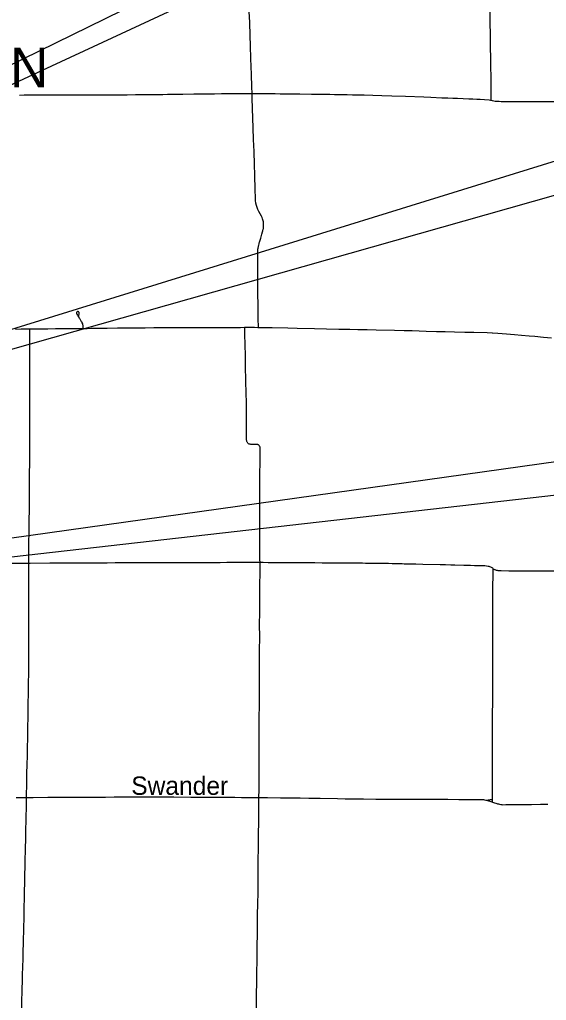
# Model space of a CAD drawing. Extents: x 1772825 to 1773716, y 1138558 to 1139032.
# Drawn here: x 1773418.9 to 1773464.2, y 1138829.3 to 1138913.7 of the extents above; entities that cross this region are included whole.
import ezdxf

# ---------------------------------------------------------------- set-up
doc = ezdxf.new("R2010")
doc.units = 0
for name, color, linetype in [('GM_X_County_Road', 7, 'Continuous'), ('GM_X_State_Route', 7, 'Continuous'), ('GM_X_Township_Road', 7, 'Continuous'), ('GM_X_Township_Text', 7, 'Continuous'), ('GM_X_Unincorporated_Text', 7, 'Continuous'), ('SH_Text', 7, 'Continuous')]:
    doc.layers.add(name, color=color, linetype=linetype)

msp = doc.modelspace()

# ---------------------------------------------------------------- linework, layer by layer
at = {"layer": 'GM_X_County_Road'}
for points in [[(1773459.466, 1138906.727), (1773459.463, 1138907.253), (1773459.452, 1138908.782), (1773459.442, 1138909.524), (1773459.431, 1138910.407), (1773459.42, 1138911.215), (1773459.408, 1138912.222), (1773459.38, 1138913.514), (1773459.377, 1138914.41), (1773459.362, 1138915.504), (1773459.358, 1138915.951), (1773459.347, 1138916.685), (1773459.32, 1138918.12), (1773459.275, 1138920.638), (1773459.261, 1138921.334), (1773459.249, 1138921.744), (1773459.231, 1138922.589), (1773459.214, 1138923.403), (1773459.198, 1138924.181), (1773459.16, 1138926.244), (1773459.162, 1138926.691)], [(1773439.599, 1138866.982), (1773439.593, 1138867.207), (1773439.587, 1138867.394), (1773439.587, 1138867.722), (1773439.58, 1138868.537), (1773439.587, 1138869.854), (1773439.586, 1138871.209), (1773439.589, 1138872.514), (1773439.59, 1138873.782), (1773439.591, 1138874.714), (1773439.6, 1138875.448), (1773439.611, 1138876.442), (1773439.619, 1138876.753), (1773439.614, 1138876.798), (1773439.607, 1138876.851), (1773439.601, 1138876.879), (1773439.591, 1138876.915), (1773439.58, 1138876.942), (1773439.558, 1138876.982), (1773439.53, 1138877.017), (1773439.506, 1138877.044), (1773439.47, 1138877.072), (1773439.44, 1138877.091), (1773439.408, 1138877.105), (1773439.374, 1138877.113), (1773439.325, 1138877.119), (1773439.243, 1138877.122), (1773438.906, 1138877.117), (1773438.805, 1138877.122), (1773438.752, 1138877.129), (1773438.716, 1138877.136), (1773438.662, 1138877.153), (1773438.619, 1138877.174), (1773438.581, 1138877.2), (1773438.546, 1138877.228), (1773438.507, 1138877.277), (1773438.481, 1138877.326), (1773438.466, 1138877.364), (1773438.451, 1138877.415), (1773438.441, 1138877.477), (1773438.442, 1138877.539), (1773438.444, 1138878.224), (1773438.441, 1138878.944), (1773438.438, 1138879.749), (1773438.423, 1138880.667), (1773438.386, 1138882.493), (1773438.351, 1138883.934), (1773438.336, 1138884.778), (1773438.291, 1138886.606), (1773438.279, 1138887.099), (1773438.277, 1138887.19)], [(1773419.727, 1138866.916), (1773419.843, 1138866.918), (1773421.52, 1138866.926), (1773422.455, 1138866.929), (1773422.664, 1138866.931), (1773422.813, 1138866.932), (1773423.061, 1138866.933), (1773423.668, 1138866.934), (1773423.88, 1138866.934), (1773424.091, 1138866.935), (1773424.364, 1138866.937), (1773424.749, 1138866.937), (1773425.706, 1138866.945), (1773426.452, 1138866.946), (1773427.149, 1138866.954), (1773427.77, 1138866.956), (1773428.28, 1138866.959), (1773428.839, 1138866.962), (1773429.635, 1138866.966), (1773430.394, 1138866.972), (1773431.077, 1138866.971), (1773432.445, 1138866.978), (1773433.713, 1138866.978), (1773434.645, 1138866.976), (1773435.242, 1138866.978), (1773435.677, 1138866.977), (1773436.174, 1138866.979), (1773436.746, 1138866.98), (1773437.206, 1138866.982), (1773437.914, 1138866.983), (1773438.424, 1138866.983), (1773438.61, 1138866.982), (1773438.709, 1138866.983), (1773438.784, 1138866.982), (1773439.206, 1138866.981), (1773439.468, 1138866.982), (1773439.599, 1138866.982)], [(1773439.505, 1138846.749), (1773439.51, 1138847.409), (1773439.518, 1138848.363), (1773439.517, 1138849.159), (1773439.523, 1138850.427), (1773439.525, 1138850.936), (1773439.533, 1138852.201), (1773439.535, 1138853.207), (1773439.539, 1138855.084), (1773439.539, 1138855.706), (1773439.544, 1138856.638), (1773439.545, 1138857.098), (1773439.553, 1138857.969), (1773439.561, 1138859.456), (1773439.567, 1138860.475), (1773439.566, 1138861.705), (1773439.568, 1138862.575), (1773439.581, 1138864.066), (1773439.587, 1138864.899), (1773439.604, 1138866.217), (1773439.604, 1138866.603), (1773439.6, 1138866.93), (1773439.599, 1138866.982)], [(1773439.599, 1138866.982), (1773439.642, 1138866.982), (1773439.853, 1138866.982), (1773440.3, 1138866.978), (1773440.723, 1138866.978), (1773441.531, 1138866.975), (1773442.414, 1138866.966), (1773443.259, 1138866.962), (1773444.316, 1138866.954), (1773444.938, 1138866.95), (1773445.373, 1138866.95), (1773446.653, 1138866.944), (1773447.188, 1138866.942), (1773447.498, 1138866.939), (1773447.819, 1138866.932), (1773447.894, 1138866.932), (1773448.403, 1138866.922), (1773448.664, 1138866.917), (1773449.174, 1138866.913), (1773449.323, 1138866.91), (1773449.435, 1138866.91), (1773449.834, 1138866.91), (1773450.23, 1138866.904), (1773450.651, 1138866.899), (1773450.962, 1138866.891), (1773451.124, 1138866.887), (1773451.819, 1138866.869), (1773451.981, 1138866.862), (1773452.254, 1138866.855), (1773452.403, 1138866.852), (1773452.689, 1138866.843), (1773452.863, 1138866.838), (1773452.975, 1138866.837), (1773453.584, 1138866.829), (1773455.075, 1138866.795), (1773455.547, 1138866.78), (1773455.983, 1138866.77), (1773456.355, 1138866.759), (1773457.113, 1138866.742), (1773457.325, 1138866.735), (1773457.536, 1138866.731), (1773457.685, 1138866.726), (1773458.033, 1138866.719), (1773458.755, 1138866.704), (1773458.852, 1138866.7), (1773458.927, 1138866.696), (1773459.062, 1138866.682), (1773459.195, 1138866.66), (1773459.266, 1138866.643), (1773459.312, 1138866.629), (1773459.413, 1138866.59), (1773459.478, 1138866.561), (1773459.518, 1138866.536), (1773459.566, 1138866.503), (1773459.606, 1138866.469), (1773459.644, 1138866.431)], [(1773418.264, 1138866.898), (1773419.433, 1138866.912), (1773419.727, 1138866.916)], [(1773418.645, 1138846.756), (1773419.328, 1138846.758), (1773419.532, 1138846.759)], [(1773419.532, 1138846.759), (1773420.099, 1138846.761), (1773421.355, 1138846.775), (1773421.777, 1138846.777), (1773422.138, 1138846.779), (1773422.871, 1138846.781), (1773423.729, 1138846.791), (1773424.463, 1138846.789), (1773426.302, 1138846.791), (1773427.048, 1138846.799), (1773428.453, 1138846.801), (1773429.212, 1138846.8), (1773430.219, 1138846.799), (1773430.977, 1138846.803), (1773431.474, 1138846.805), (1773432.195, 1138846.801), (1773433.65, 1138846.788), (1773434.247, 1138846.783), (1773435.092, 1138846.777), (1773435.602, 1138846.774), (1773436.372, 1138846.774), (1773436.783, 1138846.776), (1773437.429, 1138846.774), (1773438.001, 1138846.768), (1773438.324, 1138846.761), (1773438.622, 1138846.755), (1773438.734, 1138846.754), (1773439.119, 1138846.75), (1773439.48, 1138846.749), (1773439.505, 1138846.749)], [(1773439.271, 1138826.489), (1773439.27, 1138826.524), (1773439.268, 1138827.016), (1773439.274, 1138827.537), (1773439.288, 1138828.903), (1773439.298, 1138829.661), (1773439.318, 1138831.015), (1773439.325, 1138831.624), (1773439.338, 1138832.817), (1773439.35, 1138833.973), (1773439.367, 1138835.029), (1773439.38, 1138835.911), (1773439.393, 1138836.706), (1773439.409, 1138837.588), (1773439.424, 1138838.607), (1773439.437, 1138840.397), (1773439.44, 1138841.006), (1773439.47, 1138842.772), (1773439.479, 1138843.555), (1773439.489, 1138844.71), (1773439.496, 1138846.153), (1773439.504, 1138846.687), (1773439.505, 1138846.749)], [(1773439.505, 1138846.749), (1773440.238, 1138846.743), (1773441.357, 1138846.731), (1773442.028, 1138846.724), (1773443.048, 1138846.713), (1773443.794, 1138846.701), (1773444.763, 1138846.687), (1773446.242, 1138846.663), (1773446.901, 1138846.653), (1773447.697, 1138846.64), (1773448.505, 1138846.636), (1773449.561, 1138846.622), (1773450.879, 1138846.615), (1773452.085, 1138846.609), (1773452.719, 1138846.61), (1773452.868, 1138846.609), (1773453.067, 1138846.606), (1773453.366, 1138846.603), (1773453.726, 1138846.601), (1773454.136, 1138846.601), (1773454.521, 1138846.601), (1773455.106, 1138846.6), (1773455.74, 1138846.598), (1773456.685, 1138846.596), (1773457.132, 1138846.593), (1773457.442, 1138846.59), (1773457.94, 1138846.59), (1773458.225, 1138846.591), (1773458.537, 1138846.588), (1773458.699, 1138846.581), (1773458.76, 1138846.577), (1773458.819, 1138846.568), (1773458.898, 1138846.555), (1773458.993, 1138846.532)], [(1773458.993, 1138846.532), (1773459.032, 1138846.523), (1773459.248, 1138846.461), (1773459.432, 1138846.402), (1773459.57, 1138846.362)]]:
    msp.add_lwpolyline(points, dxfattribs=at)
at = {"layer": 'GM_X_State_Route'}
for points in [[(1773420.858, 1138887.062), (1773420.876, 1138887.062), (1773421.348, 1138887.067), (1773422.007, 1138887.081), (1773422.628, 1138887.085), (1773423.187, 1138887.088), (1773423.92, 1138887.094), (1773423.97, 1138887.095), (1773424.181, 1138887.095), (1773424.395, 1138887.098), (1773424.74, 1138887.101), (1773425.089, 1138887.107), (1773425.561, 1138887.113), (1773425.772, 1138887.116), (1773426.468, 1138887.128), (1773427.338, 1138887.137), (1773428.109, 1138887.146), (1773428.805, 1138887.147), (1773429.738, 1138887.156), (1773430.471, 1138887.164), (1773430.981, 1138887.174), (1773432.013, 1138887.173), (1773432.783, 1138887.177), (1773433.815, 1138887.176), (1773434.474, 1138887.18), (1773435.17, 1138887.181), (1773436.165, 1138887.188), (1773436.836, 1138887.184), (1773437.383, 1138887.187), (1773437.905, 1138887.189), (1773438.277, 1138887.19), (1773438.676, 1138887.192), (1773439.123, 1138887.19), (1773439.409, 1138887.186), (1773439.455, 1138887.185), (1773439.944, 1138887.178), (1773440.652, 1138887.168), (1773441.995, 1138887.14), (1773442.79, 1138887.121), (1773444.282, 1138887.092), (1773445.301, 1138887.068), (1773446.357, 1138887.044), (1773446.904, 1138887.035), (1773447.314, 1138887.028), (1773448.01, 1138887.014), (1773448.806, 1138886.998), (1773449.576, 1138886.976), (1773451.142, 1138886.944), (1773451.974, 1138886.922), (1773452.646, 1138886.905), (1773452.671, 1138886.904), (1773453.864, 1138886.872), (1773454.771, 1138886.845), (1773455.516, 1138886.827), (1773456.324, 1138886.806), (1773457.207, 1138886.783), (1773457.965, 1138886.762), (1773459.133, 1138886.732), (1773459.544, 1138886.715), (1773459.581, 1138886.714), (1773460.04, 1138886.686), (1773460.796, 1138886.629), (1773461.478, 1138886.574), (1773462.085, 1138886.519), (1773462.716, 1138886.461), (1773463.211, 1138886.417), (1773463.954, 1138886.354), (1773464.657, 1138886.299)], [(1773418.576, 1138887.045), (1773419.074, 1138887.048), (1773419.161, 1138887.048), (1773419.372, 1138887.048), (1773419.819, 1138887.052), (1773420.858, 1138887.062)]]:
    msp.add_lwpolyline(points, dxfattribs=at)
at = {"layer": 'GM_X_Township_Road'}
for points in [[(1773438.912, 1138907.304), (1773438.902, 1138907.864), (1773438.868, 1138908.945), (1773438.819, 1138910.312), (1773438.783, 1138911.393), (1773438.75, 1138912.287), (1773438.707, 1138913.418), (1773438.678, 1138914.35)], [(1773418.917, 1138907.161), (1773419.327, 1138907.172), (1773419.712, 1138907.177), (1773419.886, 1138907.178), (1773420.023, 1138907.179), (1773420.197, 1138907.181), (1773420.482, 1138907.184), (1773420.756, 1138907.187), (1773420.967, 1138907.187), (1773421.141, 1138907.187), (1773421.887, 1138907.187), (1773422.086, 1138907.186), (1773422.297, 1138907.185), (1773422.745, 1138907.184), (1773423.279, 1138907.184), (1773423.665, 1138907.185), (1773423.901, 1138907.186), (1773424.1, 1138907.187), (1773424.261, 1138907.187), (1773424.473, 1138907.188), (1773424.783, 1138907.189), (1773425.218, 1138907.189), (1773425.492, 1138907.19), (1773425.653, 1138907.191), (1773425.865, 1138907.191), (1773426.66, 1138907.188), (1773427.493, 1138907.192), (1773428.165, 1138907.196), (1773428.898, 1138907.203), (1773429.781, 1138907.214), (1773430.738, 1138907.221), (1773431.236, 1138907.223), (1773431.658, 1138907.229), (1773432.417, 1138907.24), (1773432.976, 1138907.246), (1773433.909, 1138907.258), (1773434.468, 1138907.269), (1773434.716, 1138907.275), (1773434.828, 1138907.276), (1773435.238, 1138907.279), (1773435.673, 1138907.281), (1773436.283, 1138907.286), (1773436.63, 1138907.29), (1773437.178, 1138907.288), (1773437.439, 1138907.289), (1773437.836, 1138907.292), (1773438.01, 1138907.293), (1773438.309, 1138907.296), (1773438.912, 1138907.304)], [(1773438.912, 1138907.304), (1773438.955, 1138907.305), (1773439.514, 1138907.307), (1773439.974, 1138907.305), (1773440.223, 1138907.303), (1773440.583, 1138907.298), (1773440.894, 1138907.292), (1773441.316, 1138907.282), (1773441.814, 1138907.273), (1773442.05, 1138907.271), (1773442.61, 1138907.268), (1773443.02, 1138907.264), (1773444.014, 1138907.254), (1773444.3, 1138907.252), (1773445.083, 1138907.241), (1773445.605, 1138907.233), (1773445.991, 1138907.227), (1773446.774, 1138907.214), (1773447.085, 1138907.208), (1773447.557, 1138907.198), (1773448.539, 1138907.18), (1773449.297, 1138907.159), (1773450.08, 1138907.135), (1773450.924, 1138907.104), (1773452.092, 1138907.057), (1773453.683, 1138907), (1773454.279, 1138906.975), (1773455.211, 1138906.94), (1773455.745, 1138906.92), (1773456.155, 1138906.905), (1773456.577, 1138906.886), (1773457.558, 1138906.843), (1773457.881, 1138906.833), (1773458.242, 1138906.822), (1773458.527, 1138906.809), (1773458.899, 1138906.788), (1773459.295, 1138906.753), (1773459.405, 1138906.737), (1773459.466, 1138906.727)], [(1773439.395, 1138892.853), (1773439.395, 1138893.131), (1773439.398, 1138893.386), (1773439.401, 1138893.606), (1773439.403, 1138893.722), (1773439.41, 1138893.842), (1773439.42, 1138893.924), (1773439.429, 1138893.991), (1773439.439, 1138894.053), (1773439.454, 1138894.125), (1773439.47, 1138894.198), (1773439.487, 1138894.27), (1773439.512, 1138894.364), (1773439.537, 1138894.45), (1773439.556, 1138894.522), (1773439.656, 1138894.872), (1773439.747, 1138895.192), (1773439.813, 1138895.405), (1773439.842, 1138895.503), (1773439.869, 1138895.62), (1773439.884, 1138895.694), (1773439.898, 1138895.777), (1773439.905, 1138895.832), (1773439.91, 1138895.898), (1773439.91, 1138895.972), (1773439.909, 1138896.046), (1773439.905, 1138896.119), (1773439.895, 1138896.192), (1773439.884, 1138896.26), (1773439.864, 1138896.349), (1773439.817, 1138896.515), (1773439.771, 1138896.642), (1773439.719, 1138896.753), (1773439.604, 1138896.958), (1773439.5, 1138897.143), (1773439.42, 1138897.313), (1773439.349, 1138897.5), (1773439.295, 1138897.68), (1773439.251, 1138897.876), (1773439.222, 1138898.086), (1773439.209, 1138898.298), (1773439.187, 1138899.055), (1773439.152, 1138900.285), (1773439.122, 1138901.204), (1773439.087, 1138902.298), (1773439.048, 1138903.354), (1773439.015, 1138904.335), (1773438.961, 1138906), (1773438.919, 1138906.907), (1773438.912, 1138907.304)], [(1773459.466, 1138906.727), (1773459.564, 1138906.7), (1773459.682, 1138906.673), (1773459.82, 1138906.65), (1773459.925, 1138906.64), (1773460.004, 1138906.633), (1773460.152, 1138906.627), (1773460.33, 1138906.625), (1773461.56, 1138906.619), (1773462.592, 1138906.615), (1773463.549, 1138906.609), (1773464.643, 1138906.606), (1773465.168, 1138906.601)], [(1773439.406, 1138891.652), (1773439.403, 1138891.853), (1773439.399, 1138892.461), (1773439.395, 1138892.853)], [(1773439.455, 1138887.185), (1773439.454, 1138887.281), (1773439.446, 1138887.856), (1773439.437, 1138888.84), (1773439.423, 1138890.37), (1773439.406, 1138891.652)], [(1773424.395, 1138887.098), (1773424.389, 1138887.274), (1773424.388, 1138887.309), (1773424.383, 1138887.346), (1773424.375, 1138887.399), (1773424.354, 1138887.478), (1773424.322, 1138887.566), (1773424.297, 1138887.62), (1773424.266, 1138887.675), (1773424.237, 1138887.719), (1773424.168, 1138887.828), (1773424.127, 1138887.889), (1773424.083, 1138887.963), (1773424.041, 1138888.029), (1773424.032, 1138888.07), (1773424.03, 1138888.106), (1773424.035, 1138888.183), (1773424.053, 1138888.391), (1773424.054, 1138888.415), (1773424.053, 1138888.441), (1773424.05, 1138888.459), (1773424.045, 1138888.477), (1773424.033, 1138888.499), (1773424.017, 1138888.517), (1773423.997, 1138888.531), (1773423.962, 1138888.543), (1773423.937, 1138888.544), (1773423.913, 1138888.541), (1773423.879, 1138888.526), (1773423.864, 1138888.515), (1773423.851, 1138888.502), (1773423.833, 1138888.476), (1773423.827, 1138888.453), (1773423.825, 1138888.435), (1773423.826, 1138888.41), (1773423.833, 1138888.374), (1773423.851, 1138888.327), (1773423.902, 1138888.235), (1773423.942, 1138888.17), (1773423.98, 1138888.116), (1773424.016, 1138888.083)], [(1773419.812, 1138876.794), (1773419.811, 1138876.849), (1773419.811, 1138876.997), (1773419.812, 1138877.395), (1773419.812, 1138877.494), (1773419.813, 1138877.892), (1773419.812, 1138878.066), (1773419.813, 1138878.153), (1773419.814, 1138878.662), (1773419.817, 1138879.272), (1773419.816, 1138879.471), (1773419.814, 1138879.67), (1773419.817, 1138880.204), (1773419.817, 1138880.801), (1773419.815, 1138881.149), (1773419.813, 1138881.708), (1773419.814, 1138882.068), (1773419.816, 1138882.392), (1773419.818, 1138882.889), (1773419.818, 1138884.207), (1773419.818, 1138884.542), (1773419.82, 1138885.425), (1773419.822, 1138885.735), (1773419.822, 1138886.357), (1773419.822, 1138886.742), (1773419.82, 1138886.879), (1773419.819, 1138887.052)], [(1773419.727, 1138866.916), (1773419.727, 1138866.992), (1773419.727, 1138867.029), (1773419.727, 1138867.065), (1773419.727, 1138867.114), (1773419.726, 1138867.213), (1773419.727, 1138867.324), (1773419.728, 1138867.411), (1773419.73, 1138867.573), (1773419.731, 1138867.684), (1773419.733, 1138867.958), (1773419.735, 1138868.095), (1773419.737, 1138868.405), (1773419.738, 1138868.53), (1773419.737, 1138868.753), (1773419.737, 1138868.977), (1773419.741, 1138869.262), (1773419.756, 1138870.188), (1773419.757, 1138870.493), (1773419.766, 1138870.89), (1773419.771, 1138871.213), (1773419.776, 1138871.55), (1773419.781, 1138871.843), (1773419.78, 1138872.07), (1773419.782, 1138872.231), (1773419.785, 1138872.455), (1773419.787, 1138872.604), (1773419.785, 1138873.064), (1773419.785, 1138873.363), (1773419.784, 1138873.462), (1773419.784, 1138873.598), (1773419.785, 1138873.834), (1773419.784, 1138874.094), (1773419.786, 1138874.156), (1773419.795, 1138874.964), (1773419.798, 1138875.151), (1773419.802, 1138875.479), (1773419.806, 1138875.76), (1773419.808, 1138875.934), (1773419.809, 1138876.033), (1773419.811, 1138876.232), (1773419.81, 1138876.306), (1773419.811, 1138876.404), (1773419.813, 1138876.688), (1773419.813, 1138876.738), (1773419.812, 1138876.794)], [(1773419.532, 1138846.759), (1773419.537, 1138847.062), (1773419.546, 1138847.746), (1773419.55, 1138848.18), (1773419.564, 1138848.802), (1773419.583, 1138849.634), (1773419.598, 1138850.305), (1773419.605, 1138850.741), (1773419.634, 1138852.182), (1773419.641, 1138852.63), (1773419.649, 1138853.102), (1773419.655, 1138853.388), (1773419.663, 1138853.897), (1773419.673, 1138854.729), (1773419.683, 1138855.151), (1773419.689, 1138855.386), (1773419.692, 1138855.485), (1773419.693, 1138855.585), (1773419.695, 1138855.795), (1773419.697, 1138855.894), (1773419.698, 1138855.956), (1773419.7, 1138856.092), (1773419.7, 1138856.191), (1773419.703, 1138856.291), (1773419.704, 1138856.389), (1773419.707, 1138856.588), (1773419.707, 1138856.674), (1773419.709, 1138856.773), (1773419.709, 1138856.848), (1773419.711, 1138856.972), (1773419.713, 1138857.071), (1773419.713, 1138857.157), (1773419.714, 1138857.244), (1773419.716, 1138857.442), (1773419.716, 1138857.517), (1773419.717, 1138857.628), (1773419.72, 1138857.777), (1773419.723, 1138858.175), (1773419.724, 1138858.386), (1773419.724, 1138858.821), (1773419.725, 1138859.219), (1773419.726, 1138859.605), (1773419.724, 1138860.002), (1773419.728, 1138860.561), (1773419.732, 1138861.208), (1773419.733, 1138861.581), (1773419.731, 1138862.078), (1773419.73, 1138862.252), (1773419.729, 1138862.438), (1773419.729, 1138862.524), (1773419.732, 1138862.647), (1773419.731, 1138862.883), (1773419.735, 1138863.494), (1773419.734, 1138863.745), (1773419.734, 1138864.474), (1773419.733, 1138864.697), (1773419.731, 1138864.97), (1773419.731, 1138865.094), (1773419.73, 1138865.231), (1773419.73, 1138865.579), (1773419.731, 1138865.753), (1773419.731, 1138866.15), (1773419.731, 1138866.249), (1773419.731, 1138866.348), (1773419.73, 1138866.472), (1773419.727, 1138866.732), (1773419.726, 1138866.818), (1773419.727, 1138866.916)], [(1773459.579, 1138846.596), (1773459.589, 1138846.796), (1773459.592, 1138847.281), (1773459.587, 1138848.648), (1773459.58, 1138849.356), (1773459.575, 1138850.313), (1773459.572, 1138851.482), (1773459.587, 1138853.632), (1773459.595, 1138855.273), (1773459.6, 1138856.416), (1773459.608, 1138857.932), (1773459.61, 1138858.79), (1773459.619, 1138860.891), (1773459.615, 1138862.593), (1773459.616, 1138863.464), (1773459.619, 1138864.806), (1773459.626, 1138865.937), (1773459.629, 1138866.08), (1773459.644, 1138866.431)], [(1773459.644, 1138866.431), (1773459.691, 1138866.4), (1773459.752, 1138866.366), (1773459.785, 1138866.351), (1773459.827, 1138866.335), (1773459.897, 1138866.313), (1773459.974, 1138866.295), (1773460.031, 1138866.287), (1773460.11, 1138866.278), (1773460.229, 1138866.269), (1773460.337, 1138866.269), (1773460.995, 1138866.262), (1773461.853, 1138866.262), (1773462.873, 1138866.259), (1773463.892, 1138866.248), (1773464.986, 1138866.24)], [(1773419.246, 1138833.528), (1773419.265, 1138834.188), (1773419.299, 1138835.629), (1773419.315, 1138836.325), (1773419.324, 1138836.71), (1773419.339, 1138837.481), (1773419.343, 1138837.903), (1773419.35, 1138838.326), (1773419.357, 1138838.798), (1773419.368, 1138839.32), (1773419.377, 1138839.73), (1773419.386, 1138840.103), (1773419.402, 1138840.811), (1773419.416, 1138841.445), (1773419.433, 1138842.128), (1773419.443, 1138842.563), (1773419.454, 1138843.01), (1773419.476, 1138843.967), (1773419.497, 1138844.763), (1773419.503, 1138845.222), (1773419.516, 1138845.744), (1773419.525, 1138846.291), (1773419.532, 1138846.759)], [(1773458.993, 1138846.532), (1773459.192, 1138846.548), (1773459.28, 1138846.554), (1773459.339, 1138846.56), (1773459.411, 1138846.571), (1773459.523, 1138846.587), (1773459.579, 1138846.596)], [(1773459.57, 1138846.362), (1773459.576, 1138846.516), (1773459.579, 1138846.596)], [(1773459.57, 1138846.362), (1773459.759, 1138846.3), (1773459.862, 1138846.265), (1773459.937, 1138846.239), (1773460.014, 1138846.216), (1773460.096, 1138846.196), (1773460.178, 1138846.176), (1773460.281, 1138846.155), (1773460.372, 1138846.144), (1773460.471, 1138846.137), (1773460.715, 1138846.14), (1773462.021, 1138846.156), (1773462.928, 1138846.166), (1773463.712, 1138846.175), (1773464.345, 1138846.183)], [(1773419.049, 1138826.564), (1773419.057, 1138826.781), (1773419.061, 1138826.905), (1773419.072, 1138827.315), (1773419.083, 1138827.737), (1773419.123, 1138829.004), (1773419.134, 1138829.439), (1773419.145, 1138829.886), (1773419.16, 1138830.32), (1773419.174, 1138830.929), (1773419.192, 1138831.637), (1773419.208, 1138832.059), (1773419.235, 1138833.015), (1773419.246, 1138833.528)]]:
    msp.add_lwpolyline(points, dxfattribs=at)
at = {"layer": 'SH_Text'}
for points in [[(1773543.413, 1138971.185), (1773351.996, 1138877.306), (1773543.413, 1138966.239)], [(1773543.413, 1138925.808), (1773353.166, 1138866.864), (1773543.413, 1138920.862)], [(1773543.413, 1138886.636), (1773358.016, 1138860.614), (1773543.413, 1138881.69)]]:
    msp.add_lwpolyline(points, close=True, dxfattribs=at)

# ---------------------------------------------------------------- texts
at = {"layer": 'GM_X_Township_Text'}
msp.add_text('CLINTON', height=3.4091, rotation=0.00001, dxfattribs=at).set_placement((1773401.4, 1138907.828))
at = {"layer": 'GM_X_Unincorporated_Text'}
msp.add_text('Swander', height=1.5795, rotation=0.00001, dxfattribs=at).set_placement((1773428.529, 1138846.982))

doc.saveas('drawing.dxf')
